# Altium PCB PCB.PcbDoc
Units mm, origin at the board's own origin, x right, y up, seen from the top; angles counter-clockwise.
Board outline 41 x 25.36 mm, 2 copper layers (TOP, BOTTOM), stack 1.586 mm thick; 34 components, 14 nets, 84 pads, 45 vias.
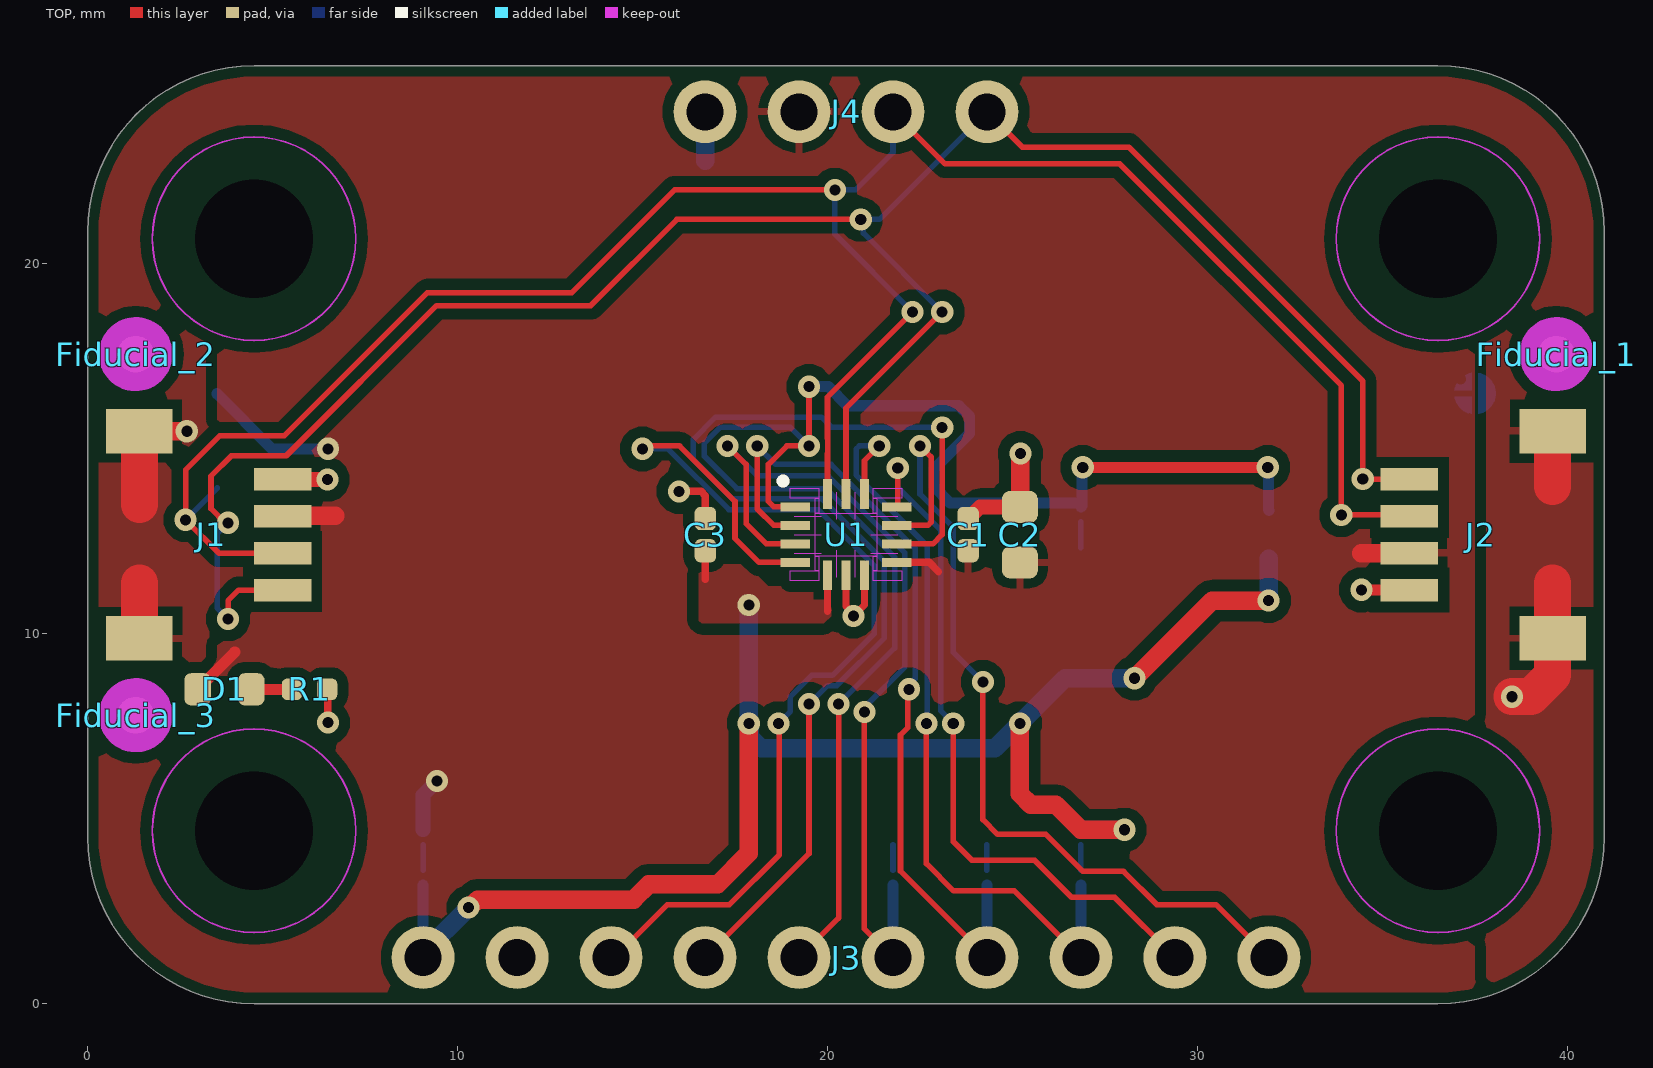
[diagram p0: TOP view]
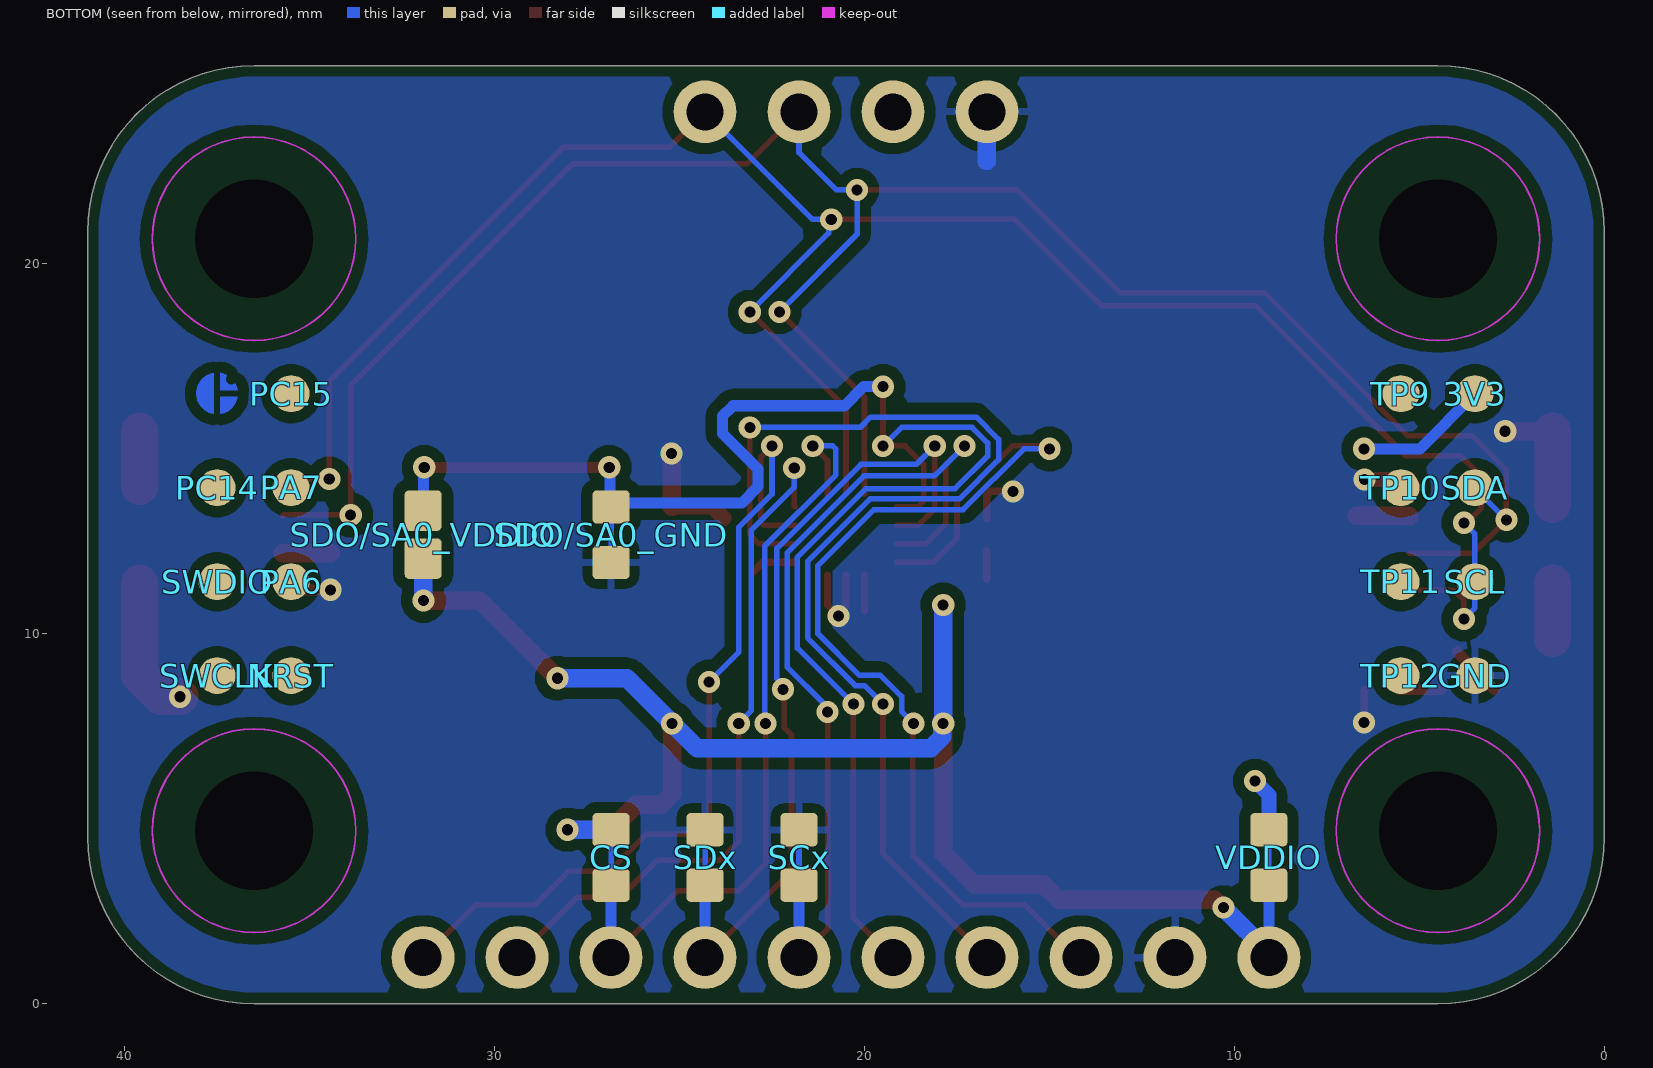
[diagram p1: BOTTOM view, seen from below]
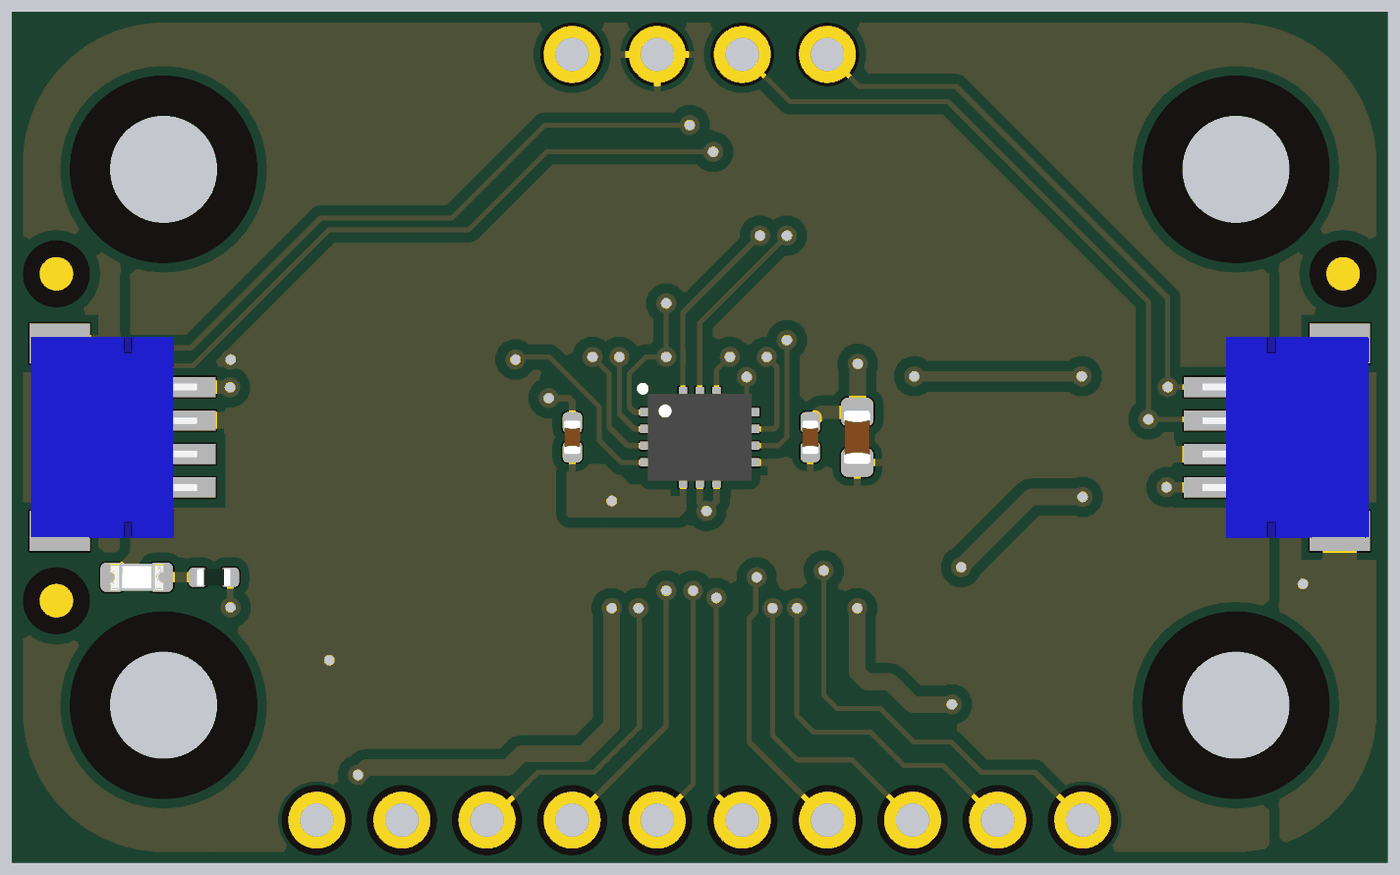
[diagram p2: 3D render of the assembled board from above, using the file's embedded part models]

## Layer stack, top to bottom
Top Solder: solder mask 0.01, Solder Resist, Dk 3.5
TOP: signal copper 0.018
Dielectric: core 1.55, FR-4, Dk 4.8
BOTTOM: signal copper 0.018
Bottom Solder: solder mask 0.01, Solder Resist, Dk 3.5

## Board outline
0,4.5 ccw(c4.5,4.5) 4.5,0 36.5,0 ccw(c36.5,4.5) 41,4.5 41,20.86 ccw(c36.5,20.86) 36.5,25.36 4.5,25.36 ccw(c4.5,20.86) 0,20.86

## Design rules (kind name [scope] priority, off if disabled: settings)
BoardOutlineClearance Mousebites [(ObjectKind = 'Pad') And (Name = 'Free-MOUSEBITE')] p1: gap=0 ignorepadtopadclearanceinfootprint=FALSE
BoardOutlineClearance Silks [(OnLayer('Top Overlay') OR OnLayer('Bottom Overlay'))] p2: gap=0 ignorepadtopadclearanceinfootprint=FALSE
BoardOutlineClearance [All] p3: gap=0.3 ignorepadtopadclearanceinfootprint=FALSE
Clearance [(ObjectKind = 'Text') And (StringType = 'Free') And (Layer = 'TOP') vs IsKeepOut] p1: gap=-2 ignorepadtopadclearanceinfootprint=FALSE
Clearance COPPER_0.3mm [All] p2: gap=0.127 ignorepadtopadclearanceinfootprint=FALSE except(0.3: Arc-Fill Arc-Poly Arc-Region Track-Fill Track-Poly Track-Region SMDPad-Fill SMDPad-Poly SMDPad-Region THPad-Fill THPad-Poly THPad-Region Via-Fill Via-Poly Via-Region Fill-Fill Fill-Poly Fill-Region Poly-Poly Poly-Region Region-Region)
Clearance "Generic clearance 0.15mm" [All] p3: gap=0.15 ignorepadtopadclearanceinfootprint=FALSE
ComponentClearance [All] p1: gap=0.2 collisioncheckmode=3 verticalgap=0 showdistances=TRUE
DiffPairsRouting USB [InDifferentialPairClass('USB')] p1: maxlimit=0.15 minlimit=0.15 mostfreqgap=0.15 toplayer_minwidth=0.15 toplayer_maxwidth=0.21 toplayer_prefwidth=0.2 bottomlayer_minwidth=0.15 bottomlayer_maxwidth=0.21 bottomlayer_prefwidth=0.2 impedanceprofiledriven=TRUE impedanceprofileid={E6B00C31-4C8E-439C-824F-D2B2CDC26F9C} impedanceprofilevalue=90.000000 maxuncoupledlength=12.7
Height [All] p1: minheight=0 maxheight=30 prefheight=12.7
HoleSize [All] p1: absolutevalues=TRUE maxlimit=30 minlimit=0.3 maxpercent=80.000 minpercent=20.000
HoleToHoleClearance [All] p1: gap=0.25 allowstackedmicrovias=FALSE
MinimumAnnularRing [All] p1: minimumring=0.15
NetAntennae NetAntennae_2 [(WithinRoom('SHORTROOM') OR WithinRoom('SHORTROOM_1') OR WithinRoom('SHORTROOM_2') OR WithinRoom('SHORTROOM_3') OR WithinRoom('SHORTROOM_4'))] p1: netantennaetolerance=2
NetAntennae [All] p2: netantennaetolerance=0
PlaneConnect [All] p1: pad.planeconnectstyle=Relief pad.reliefexpansion=0.508 pad.reliefentries=4 pad.reliefconductorwidth=0.254 pad.reliefairgap=0.254 via.planeconnectstyle=Direct via.reliefexpansion=0.508 via.reliefentries=4 via.reliefconductorwidth=0.254 via.reliefairgap=0.254
PolygonConnect [All] p1: thpad.connectstyle=Relief thpad.reliefconductorwidth=0.2 thpad.reliefentries=4 thpad.polygonreliefangle="90 Angle" thpad.airgapwidth=0.254 smdpad.connectstyle=Relief smdpad.reliefconductorwidth=0.2 smdpad.reliefentries=4 smdpad.polygonreliefangle="90 Angle" smdpad.airgapwidth=0.254 via.connectstyle=Direct via.reliefconductorwidth=0.254 via.reliefentries=4 via.polygonreliefangle="90 Angle" via.airgapwidth=0.254
RoomDefinition SHORTROOM_4 [False vs False] p1: confinementstyle=ConfineIn formatcopy=TRUE lockcomponents=FALSE outline 26.45,13.73 27.25,13.73 27.25,11.63 26.45,11.63
RoomDefinition SHORTROOM_3 [False vs False] p2: confinementstyle=ConfineIn formatcopy=TRUE lockcomponents=FALSE outline 8.66,5 9.46,5 9.46,2.9 8.66,2.9
RoomDefinition SHORTROOM_2 [False vs False] p3: confinementstyle=ConfineIn formatcopy=TRUE lockcomponents=FALSE outline 26.45,5.005 27.25,5.005 27.25,2.905 26.45,2.905
RoomDefinition SHORTROOM_1 [False vs False] p4: confinementstyle=ConfineIn formatcopy=TRUE lockcomponents=FALSE outline 23.91,5.005 24.71,5.005 24.71,2.905 23.91,2.905
RoomDefinition SHORTROOM [False vs False] p5: confinementstyle=ConfineIn formatcopy=TRUE lockcomponents=FALSE outline 21.37,5.005 22.17,5.005 22.17,2.905 21.37,2.905
RoomDefinition TOP [InComponentClass('TOP')] p6: confinementstyle=ConfineIn formatcopy=TRUE lockcomponents=FALSE outline 45.1,1.2 58.1,1.2 58.1,13.6 45.1,13.6
RoutingVias StandardVias [All] p1: holewidth=0.3 width=0.6 viastyle="Through Hole" minholewidth=0.3 minwidth=0.6 maxholewidth=0.3 maxwidth=0.6
SMDToCorner [All] p1: distance=39370
ShortCircuit short_jumper [(WithinRoom('SHORTROOM') OR WithinRoom('SHORTROOM_1') OR WithinRoom('SHORTROOM_2') OR WithinRoom('SHORTROOM_3') OR WithinRoom('SHORTROOM_4')) vs (WithinRoom('SHORTROOM') OR WithinRoom('SHORTROOM_1') OR WithinRoom('SHORTROOM_2') OR WithinRoom('SHORTROOM_3') OR WithinRoom('SHORTROOM_4'))] p1: allowed=TRUE
ShortCircuit ShortCircuit_1 [(ObjectKind = 'Pad') And (Layer = 'TOP') And (Net = 'GND') And (Name = 'SJ2-2')] p2: allowed=TRUE
ShortCircuit [All] p3: allowed=FALSE
SilkToSilkClearance [All] p1: silktosilkclearance=0.2
SilkToSolderMaskClearance [IsPad] p1: minsilkscreentomaskgap=0.15 clearancetoexposedcopper=TRUE
SolderMaskExpansion VIAtented [IsVia] p1: expansion=0.102 istentingtop=TRUE
SolderMaskExpansion [All] p2: expansion=0.05 istentingtop=FALSE
UnConnectedPin [All] p1:
UnRoutedNet [NOT WithinRoom('K36')] p1: checkbadconnections=TRUE
ViasUnderSMD [All] p1: allowed=FALSE
Width StandardTraces [All] p1: maxlimit=5 minlimit=0.15 preferedwidth=0.15 minimp=50.000000 maximp=50.000000 favimp=50.000000
19 further rules are at their usual default settings.

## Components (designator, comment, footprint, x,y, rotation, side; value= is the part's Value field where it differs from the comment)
3V3 "Test point 1.00mm" TP-1.00MM 3.5,16.49 r90 bottom
C1 "0402B104K160CT" CAP-0402 23.8,12.68 r90 top value=100nF
C2 "GRM188R61C475KAAJD" CAP-0603 25.2,12.68 r270 top value=4.7µF
C3 "0402B104K160CT" CAP-0402 16.7,12.68 r90 top value=100nF
CS "SOLDER JUMPER CLOSED 0603" "SJ 0603 CLOSED" 26.85,3.955 r270 bottom
D1 "HSMG-C190" LEDC1608X80N-AK 3.7,8.5 r180 top
Fiducial_1 "Fiducial mark 1mm" "Fiducial mark 1mm-Footprint-1" 39.7,17.56 r270 top
Fiducial_2 "Fiducial mark 1mm" "Fiducial mark 1mm-Footprint-1" 1.3,17.56 r270 top
Fiducial_3 "Fiducial mark 1mm" "Fiducial mark 1mm-Footprint-1" 1.3,7.8 r270 top
GND "Test point 1.00mm" TP-1.00MM 3.5,8.87 r90 bottom
J1 "SM04B-SRSS-TB(LF)(SN)" SM04B-SRSS-TB(LF)(SN)-Footprint-1 3.337,12.68 r90 top locked
J2 "SM04B-SRSS-TB(LF)(SN)" SM04B-SRSS-TB(LF)(SN)-Footprint-1 37.663,12.68 r270 top locked
J3 "HEADER TH 2.54mm VERT. 1x010POS" "PIN HEADER 2.54mm VERT. 1x10POS" 20.5,1.25 r0 top
J4 "HEADER TH 2.54mm VERT. 1x004POS" "PIN HEADER 2.54mm VERT. 1x4POS-Footprint-1" 20.5,24.11 r0 top
NRST "Test point 1.00mm" TP-1.00MM 35.5,8.87 r180 bottom
PA6 "Test point 1.00mm" TP-1.00MM 35.5,11.41 r180 bottom
PA7 "Test point 1.00mm" TP-1.00MM 35.5,13.95 r180 bottom
PC14 "Test point 1.00mm" TP-1.00MM 37.5,13.95 r180 bottom
PC15 "Test point 1.00mm" TP-1.00MM 35.5,16.49 r180 bottom
R1 "CRCW04021K00FKEDC" RES-0402 6,8.5 r180 top value=1k
SCL "Test point 1.00mm" TP-1.00MM 3.5,11.41 r90 bottom
SCx "SOLDER JUMPER CLOSED 0603" "SJ 0603 CLOSED" 21.77,3.955 r270 bottom
SDA "Test point 1.00mm" TP-1.00MM 3.5,13.95 r90 bottom
SDO/SA0_GND "SOLDER JUMPER CLOSED 0603" "SJ 0603 CLOSED" 26.85,12.68 r90 bottom
SDO/SA0_VDDIO "SOLDER JUMPER OPEN 0603" SJ 31.93,12.68 r90 bottom
SDx "SOLDER JUMPER CLOSED 0603" "SJ 0603 CLOSED" 24.31,3.955 r270 bottom
SWCLK "Test point 1.00mm" TP-1.00MM 37.5,8.87 r180 bottom
SWDIO "Test point 1.00mm" TP-1.00MM 37.5,11.41 r180 bottom
TP9 "Test point 1.00mm" TP-1.00MM 5.5,16.49 r0 bottom
TP10 "Test point 1.00mm" TP-1.00MM 5.5,13.95 r0 bottom
TP11 "Test point 1.00mm" TP-1.00MM 5.5,11.41 r0 bottom
TP12 "Test point 1.00mm" TP-1.00MM 5.5,8.87 r0 bottom
U1 "LSM6DSOXTR" LSM6DSOXTR 20.5,12.68 r0 top
VDDIO "SOLDER JUMPER CLOSED 0603" "SJ 0603 CLOSED" 9.07,3.955 r90 bottom

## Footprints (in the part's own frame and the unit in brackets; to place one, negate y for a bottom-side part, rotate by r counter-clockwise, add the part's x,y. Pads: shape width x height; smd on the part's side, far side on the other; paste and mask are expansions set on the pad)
CAP-0402 [mm] "Chip Capacitor, 2-Leads, Body  0402 (in) 1005 (mm), IPC Medium Density"
  rrect52% 0.63x0.58 smd mask+0.05: 1(-0.435,0) 2(0.435,0)
  body extent -0.5,-0.25 0.5,0.25, height 0.5
CAP-0603 [mm] "Chip Capacitor, Body 0603 imperial,1.6x0.8mm, IPC High Density"
  rrect51% 0.87x0.97 smd mask+0.05: 1(-0.75,0) 2(0.75,0)
  body extent -0.8,-0.4 0.8,0.4, height 0.8
"Fiducial mark 1mm-Footprint-1" [mm]
  round 1 smd paste-10 mask+0.5: 1(0,0)
  TOP keep-out circle w1: c0,0 r0.5
LEDC1608X80N-AK [mm]
  rrect50% 0.72x0.87 smd: A(0.725,0) C(-0.725,0)
  body extent -0.8,-0.4 0.8,0.4, height 0.79
LSM6DSOXTR [mm]
  rect 0.8x0.25 smd mask+0.05: 1(-1.375,0.75) 2(-1.375,0.25) 3(-1.375,-0.25) 4(-1.375,-0.75) 8(1.375,-0.75) 9(1.375,-0.25) 10(1.375,0.25) 11(1.375,0.75)
  rect 0.25x0.8 smd mask+0.05: 5(-0.5,-1.1) 6(0,-1.1) 7(0.5,-1.1) 12(0.5,1.1) 13(0,1.1) 14(-0.5,1.1)
  TOP keep-out region: -0.83,-0.98 -0.83,-0.58 -0.74,-0.58 -0.74,-0.98
  TOP keep-out region: 0.74,-0.98 0.74,-0.58 0.83,-0.58 0.83,-0.98
  TOP keep-out region: 0.74,0.58 0.74,0.98 0.83,0.98 0.83,0.58
  TOP keep-out region: -0.83,0.58 -0.83,0.98 -0.74,0.98 -0.74,0.58
  TOP keep-out region: -1.5,-1.25 -1.5,-0.98 -0.74,-0.98 -0.74,-1.25
  TOP keep-out region: 0.74,-1.25 0.74,-0.98 1.5,-0.98 1.5,-1.25
  TOP keep-out region: 0.74,0.98 0.74,1.25 1.5,1.25 1.5,0.98
  TOP keep-out region: -1.5,0.98 -1.5,1.25 -0.74,1.25 -0.74,0.98
  TOP keep-out region: -0.83,-0.58 -0.83,0.58 0.83,0.58 0.83,-0.58
  TOP keep-out lines w0.01: -1.4,-0.5 -0.67,-0.5 ; -1.4,0 -0.67,0 ; -1.4,0.5 -0.67,0.5 ; -0.25,-1.15 -0.25,-0.42 ; -0.25,0.42 -0.25,1.15 ; 0.25,-1.15 0.25,-0.42 ; 0.25,0.42 0.25,1.15 ; 0.67,-0.5 1.4,-0.5 ; 0.67,0 1.4,0 ; 0.67,0.5 1.4,0.5
  silkscreen extent -1.75,1.4 -1.65,1.5, body extent -1.55,-1.3 1.55,1.3, height 0.86
"PIN HEADER 2.54mm VERT. 1x4POS-Footprint-1" [mm]
  round 1.7 hole 1 mask+0.1: 1(-3.81,0) 2(-1.27,0) 3(1.27,0) 4(3.81,0)
"PIN HEADER 2.54mm VERT. 1x10POS" [mm]
  round 1.7 hole 1 mask+0.2: 1(-11.43,0) 2(-8.89,0) 3(-6.35,0) 4(-3.81,0) 5(-1.27,0) 6(1.27,0) 7(3.81,0) 8(6.35,0) 9(8.89,0) 10(11.43,0)
RES-0402 [mm] "Chip Resistor, 2-Leads, Body  0402 (in) 1005 (mm), IPC Medium Density"
  rrect51% 0.55x0.58 smd mask+0.05: 1(-0.475,0) 2(0.475,0)
  body extent -0.5,-0.25 0.5,0.25, height 0.34
SJ [mm]
  rrect25% 1.1x1 smd paste-2539.97 mask+0.1: 1(0.65,0) 2(-0.65,0)
"SJ 0603 CLOSED" [mm]
  rrect25% 0.9x1 smd paste-2539.97 mask+0.1: 1(0.75,0) 2(-0.75,0)
  TOP lines w0.15: 0.35,0 -0.35,0
SM04B-SRSS-TB(LF)(SN)-Footprint-1 [mm]
  rect 0.6x1.55 smd mask+0.05: 1(1.5,-1.937) 2(0.5,-1.937) 3(-0.5,-1.937) 4(-1.5,-1.937)
  rect 1.2x1.8 smd mask+0.05: FIX(-2.8,1.938) FIX(2.8,1.938)
  body extent -3,-2.16 3,2.8, height 2.98
TP-1.00MM [mm]
  rrect100% 1x1 smd paste-2.54: X(0,0)

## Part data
3V3 GND NRST PA6 PA7 PC14 PC15 SCL SDA SWCLK SWDIO TP9 TP10 TP11 TP12: library part UT0013-A.6, Manufacturer="This is not a component"
C1 C3: library part C0012-A.15, "CAP CHIP 0402 100nF 10% 16V X7R", Case Code (Imperial)=0402, Dielectric=X7R, Manufacturer=Walsin, Tolerance=10%, Voltage=16V
C2: library part C0054-A.16, "CAP CHIP 0603 4.7uF 10% 16V X5R", Case Code (Imperial)=0603, Dielectric=X5R, Manufacturer=Murata, Manufacturer 3="Samsung Electro-Mechanics", Part number 2=GRM188R61C475KE11D, Part number 3=CL10A475KO8NNNC, Tolerance=10%, Voltage=16V
CS SCx SDO/SA0_GND SDx VDDIO: library part UT0039-A.3
D1: library part L0009-A.5, "LED SMD 0603 GREEN/568 15mcd 120^", Manufacturer=Broadcom
Fiducial_1 Fiducial_2 Fiducial_3: library part UT0023-A.7, "Fiducial mark 1mm clearance 2mm"
J1 J2: library part J0005-A.2, "CONN JST 4POS SIDE 1MM TIN QWIIC", Manufacturer=JST
J3: library part J0169-A.8
J4: library part J0162-A.5
R1: library part R0007-A.24, "RES CHIP 0402 1k 1% 1/16W", Case Code (Imperial)=0402, Manufacturer=Vishay, Power=62.5mW, Temperature Coefficient=100ppm, Tolerance=1%
SDO/SA0_VDDIO: library part UT0038-A.4
U1: library part U0179-A.10, "IC IMU 6 axis, 9kB data buffering, event/tilt detection, sensor hub, VDD 1.71V to 3.6V, VDDIO 1.62V to 3.6V, I2C/SPI, auxiliary SPI, LGA14 3x2.5x0.86mm", Manufacturer="ST Microelectronics"

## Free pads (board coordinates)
  round 3 hole 3.2 unplated paste-2539.97 mask-2539.97: MH(4.5,4.68)
  round 3 hole 3.2 unplated paste-2539.97 mask+1.3: MH(4.5,20.68) MH(36.5,4.68) MH(36.5,20.68)

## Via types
v1: diameter 0.6, hole 0.3, TOP to BOTTOM, tented both sides, 44 vias
v2: diameter 0.6, hole 0.3, TOP to BOTTOM, 1 vias

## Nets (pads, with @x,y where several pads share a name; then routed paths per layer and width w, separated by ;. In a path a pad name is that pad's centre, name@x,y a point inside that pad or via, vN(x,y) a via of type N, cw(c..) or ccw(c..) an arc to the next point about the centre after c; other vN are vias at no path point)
+3V3: 3V3.X C1.1 C2.2 D1.A J1.2 J2.2 J4.2 U1.8 VDDIO.1 | length 10.5
  TOP w0.2: U1.8 22.75,11.93 23,11.68
  TOP w0.3: D1.A 3.98,9.505
  TOP w0.5: J1.2 5.284,13.19 6.69,13.19 ; 34.42,12.18 J2.2
  BOTTOM w0.3: 3V3.X 4.99,15 v1(6.5,15)
  BOTTOM w0.4: VDDIO.1 9.07,5.647 v1(9.447,6.024)
CS_1: CS.1 J3.8 U1.12 | length 21.3
  TOP w0.15: U1.12 21,14.68 v1(21.4,15.08) ; v1(22.673,7.58) 22.673,3.787 23.41,3.05 25.05,3.05 J3.8
  BOTTOM w0.15: v1(21.4,15.08) 20.861,15.08 20.773,14.992 20.773,14.295 22.702,12.366 22.702,7.609 v1(22.673,7.58)
  BOTTOM w0.3: J3.8 CS.1
GND: C1.2 C2.1 C3.2 GND.X J1.1 J1.FIX J2.1 J2.FIX J3.2 J4.1 R1.1 SCx.2 SDO/SA0_GND.2 SDx.2 U1.6 U1.7 | length 21.6
  TOP w0.2: R1.1 6.488,8.488 6.488,7.612 v1(6.5,7.6) ; v1(15.99,13.85) 16.583,13.85 16.7,13.733 C3.2 ; U1.6 20.5,10.742 20.6,10.641 20.6,10.58 v1(20.7,10.48) 21,10.78 U1.7
  TOP w0.3: v1(34.43,11.19) 34.435,11.185 35.721,11.185 J2.1
  TOP w0.4: J1.1 5.279,14.175 6.479,14.175 v1(6.484,14.171) ; C1.2 23.8,13.14 23.89,13.23 23.924,13.23 24.124,13.43 24.965,13.43 C2.1
  TOP w0.5: J1.FIX@1.399,15.48 2.678,15.48 v1(2.683,15.475) ; C2.1 25.208,13.438 25.208,14.866 v1(25.215,14.874)
  TOP w1: J1.FIX@1.399,9.88 1.399,11.379 ; 1.399,13.499 J1.FIX@1.399,15.48 ; v1(38.5,8.3) 39.015,8.3 39.601,8.886 J2.FIX@39.601,9.88 ; J2.FIX@39.6,9.881 39.6,11.38 ; 39.601,13.981 J2.FIX@39.601,15.48
  BOTTOM w0.5: 16.69,22.79 J4.1
INT1_1: J3.3 U1.4 | length 28.5
  TOP w0.15: J3.3 14.243,1.25 15.673,2.68 17.35,2.68 18.696,4.026 18.696,7.557 v2(18.673,7.58) ; v1(15,15) 15.08,15.08 16,15.08 17.5,13.58 17.5,12.58 18.15,11.93 U1.4
  BOTTOM w0.15: v1(15,15) 15.69,15 17.332,13.358 19.747,13.358 21.259,11.846 21.259,10.003 20.135,8.879 19.569,8.879 18.998,8.308 18.998,7.905 v2(18.673,7.58)
INT2_1: J3.4 U1.9 | length 31
  TOP w0.15: J3.4 19.5,4.06 v1(19.5,8.1) ; U1.9 22.85,12.43 23.1,12.68 v1(23.1,15.58)
  BOTTOM w0.15: v1(19.5,8.1) 20.002,8.602 20.249,8.602 21.536,9.888 21.536,11.961 19.85,13.646 17.435,13.646 16.373,14.709 16.373,15.255 16.977,15.859 19.838,15.859 20.115,15.582 23.098,15.582 v1(23.1,15.58)
NetD1_C: D1.C R1.2 | length 1.1
  TOP w0.3: D1.C R1.2
OCS_Aux_1: J3.10 U1.10 | length 23.2
  TOP w0.15: U1.10 22.712,12.93 22.8,13.018 22.8,14.78 v1(22.5,15.08) ; v1(24.2,8.7) 24.2,4.98 24.6,4.58 25.9,4.58 26.9,3.58 28,3.58 28.9,2.68 30.5,2.68 J3.10
  BOTTOM w0.15: v1(22.5,15.08) 22.5,13.778 23.4,12.878 23.4,9.5 v1(24.2,8.7)
SCL_1: J1.4 J2.4 J4.4 SCL.X U1.13 | length 58
  TOP w0.15: v1(3.8,10.4) 3.8,10.9 4.08,11.18 J1.4 ; v1(3.8,13) 3.723,13 3.337,13.386 3.337,14.262 3.888,14.813 5.371,14.813 9.431,18.874 13.601,18.874 15.927,21.2 v1(20.9,21.2) ; U1.13 20.5,16.1 v1(23.1,18.7) ; J4.4 25.263,23.157 28.143,23.157 34.468,16.832 v1(34.468,14.182) J2.4 J2.4
  BOTTOM w0.15: v1(3.8,10.4) 3.5,10.7 3.5,12.7 v1(3.8,13) ; v1(23.1,18.7) 20.971,20.829 20.971,21.129 v1(20.9,21.2) 21.4,21.2 J4.4
SCx_1: J3.6 SCx.1 U1.3 | length 23.5
  TOP w0.15: v1(17.3,15.08) 17.8,14.58 17.8,12.98 18.35,12.43 U1.3 ; v1(20.996,7.884) 20.996,2.024 J3.6
  BOTTOM w0.15: v1(17.3,15.08) 18.113,14.267 20.013,14.267 22.091,12.189 22.091,9.101 v1@21.086,8.096 ; v1(20.996,7.884) 20.996,8.006 v1@21.086,8.096
  BOTTOM w0.3: J3.6 SCx.1
SDA_1: J1.3 J2.3 J4.3 SDA.X U1.14 | length 59.9
  TOP w0.15: 2.65,14.44 v1(2.65,13.082) 3.554,12.178 3.895,12.178 3.897,12.18 J1.3 ; 2.66,14.44 3.569,15.349 5.313,15.349 9.187,19.224 13.092,19.224 15.868,22 v1(20.2,22) ; U1.14 20,14.87 20.002,14.872 20.002,15.288 20,15.29 20,16.4 v1(22.3,18.7) ; J4.3 23.18,22.7 27.9,22.7 33.887,16.713 v1(33.887,13.215) 35.69,13.215 J2.3
  BOTTOM w0.15: v1(2.65,13.082) 3.5,13.932 SDA.X ; J4.3 21.77,23.01 20.76,22 v1(20.2,22) 20.2,20.8 v1(22.3,18.7)
SDO/SA0_1: J3.5 SDO/SA0_GND.1 SDO/SA0_VDDIO.1 U1.1 | length 44.7
  TOP w0.15: U1.1 18.55,13.43 18.4,13.58 18.4,14.58 18.9,15.08 v1(19.5,15.08) v1(19.5,16.68) ; J3.5 20.3,2.32 v1(20.3,8.1)
  TOP w0.3: v1(26.9,14.5) v1(31.9,14.5)
  BOTTOM w0.15: v1(19.5,15.08) 18.998,15.582 17.092,15.582 16.673,15.163 16.673,14.8 17.55,13.923 19.965,13.923 21.814,12.074 21.814,9.614 v1(20.3,8.1)
  BOTTOM w0.3: v1(19.5,16.68) 20.025,16.68 20.541,16.164 23.558,16.164 23.836,15.887 23.836,15.417 22.873,14.455 22.873,13.977 23.311,13.539 SDO/SA0_GND.1@26.752,13.539 ; SDO/SA0_GND.1 26.875,13.455 26.875,14.475 v1(26.9,14.5) ; v1(31.9,14.5) 31.915,14.485 31.915,13.345 SDO/SA0_VDDIO.1
SDO_Aux_1: J3.9 U1.11 | length 19.1
  TOP w0.15: U1.11 21.9,13.455 v1(21.9,14.48) ; v1(23.4,7.58) 23.4,4.38 23.9,3.88 25.6,3.88 26.6,2.88 27.76,2.88 J3.9
  BOTTOM w0.15: v1(21.9,14.48) 21.9,13.959 23.057,12.802 23.057,7.923 v1(23.4,7.58)
SDx_1: J3.7 SDx.1 U1.2 | length 22.5
  TOP w0.15: v1(18.1,15.08) 18.1,13.38 18.55,12.93 U1.2 ; v1(22.2,8.5) 22.171,8.471 22.171,7.465 21.973,7.267 21.973,3.587 J3.7
  BOTTOM w0.15: v1(18.1,15.08) 18.602,14.578 20.099,14.578 22.368,12.309 22.368,8.79 22.2,8.622 v1(22.2,8.5)
  BOTTOM w0.3: J3.7 SDx.1
VDDIO: C3.1 CS.2 J3.1 SDO/SA0_VDDIO.2 U1.5 VDDIO.2 | length 44.1
  TOP w0.2: 16.7,11.48 C3.1 ; 20,10.615 U1.5
  TOP w0.5: v1(10.3,2.6) 10.327,2.6 10.545,2.818 14.76,2.818 15.168,3.227 17.027,3.227 17.873,4.073 v1(17.873,7.58) ; v1(25.2,7.58) 25.2,5.673 25.493,5.38 26.175,5.38 26.85,4.705 v1(28.025,4.705) ; v1(28.3,8.8) 30.399,10.899 v1(31.923,10.899)
  BOTTOM w0.3: J3.1 VDDIO.2
  BOTTOM w0.5: J3.1 9.07,1.37 v1@10.281,2.581 ; v1@17.873,7.553 v1(17.873,10.78) ; v1(17.873,7.58) 17.892,7.561 17.892,7.227 18.216,6.903 24.523,6.903 26.42,8.8 v1(28.3,8.8) ; CS.2 v1(28.025,4.705) ; v1(31.923,10.899) 31.927,10.903 31.927,12.027 SDO/SA0_VDDIO.2
pads on no net: Fiducial_1.1 Fiducial_2.1 Fiducial_3.1 NRST.X PA6.X PA7.X PC14.X PC15.X SWCLK.X SWDIO.X TP9.X TP10.X TP11.X TP12.X

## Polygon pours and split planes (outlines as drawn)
GND on TOP "NONET_L04_P-001" (solid, remove dead copper, pour order 5): 0,4.5 ccw(c4.5,4.5) 4.5,0 36.5,0 ccw(c36.5,4.5) 41,4.5 41,20.86 ccw(c36.5,20.86) 36.5,25.36 4.5,25.36 ccw(c4.5,20.86) 0,20.86
+3V3 on TOP "NONET_L04_P-001" (solid, remove dead copper, pour order 3): 0,4.5 ccw(c4.5,4.5) 4.5,0 36.5,0 ccw(c36.5,4.5) 41,4.5 41,20.86 ccw(c36.5,20.86) 36.5,25.36 4.5,25.36 ccw(c4.5,20.86) 0,20.86
VDDIO on TOP "VDDIO_L01_P000" (solid, remove dead copper, pour order 0): 20.2,12.08 20.2,10.58 19.9,10.28 16.6,10.28 16.522,10.358 16.522,11.88 17.8,11.88 18.4,11.28 19.7,11.28 19.7,12.08
GND on TOP "NONET_L04_P-001" (solid, remove dead copper, pour order 2): 0,25.36 0,0 3.2,0 3.2,25.36
GND on TOP "NONET_L04_P-001" (solid, remove dead copper, pour order 1): 41,25.36 41,0 37.8,0 37.8,25.36
GND on BOTTOM "NONET_L04_P-001" (solid, remove dead copper, pour order 4): 0,4.5 ccw(c4.5,4.5) 4.5,0 36.5,0 ccw(c36.5,4.5) 41,4.5 41,20.86 ccw(c36.5,20.86) 36.5,25.36 4.5,25.36 ccw(c4.5,20.86) 0,20.86

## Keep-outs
Keep-Out Layer:
  circle w0.05: c4.5,20.68 r2.75
  circle w0.05: c4.5,4.68 r2.75
  circle w0.05: c36.5,20.68 r2.75
  circle w0.05: c36.5,4.68 r2.75

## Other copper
BOTTOM:
  region: 37.415,16.266 37.415,15.955 37.408,15.955 37.408,15.949 37.382,15.949 37.382,15.955 37.375,15.955 37.375,15.962 37.335,15.962 37.335,15.969 37.309,15.969 37.309,15.975 37.302,15.975 37.302,15.982 37.289,15.982 37.289,15.989 37.282,15.989 37.282,15.995 37.269,15.995 37.269,15.989 37.256,15.989 37.256,16.002 37.236,16.002 37.236,16.008 37.229,16.008 37.229,16.015 37.223,16.015 37.223,16.022 37.203,16.022 37.203,16.028 37.196,16.028 37.196,16.035 37.183,16.035 37.183,16.041 37.177,16.041 37.177,16.048 37.17,16.048 37.17,16.055 37.157,16.055 37.157,16.068 37.137,16.068 37.137,16.075 37.13,16.075 37.13,16.081 37.124,16.081 37.124,16.088 37.117,16.088 37.117,16.094 37.11,16.094 37.11,16.101 37.104,16.101 37.104,16.108 37.097,16.108 37.097,16.114 37.091,16.114 37.091,16.121 37.084,16.121 37.084,16.127 37.077,16.127 37.077,16.134 37.071,16.134 37.071,16.154 37.064,16.154 37.064,16.161 37.057,16.161 37.057,16.167 37.051,16.167 37.051,16.174 37.044,16.174 37.044,16.187 37.038,16.187 37.038,16.194 37.031,16.194 37.031,16.2 37.024,16.2 37.024,16.207 37.018,16.207 37.018,16.227 37.011,16.227 37.011,16.247 36.998,16.247 36.998,16.266 36.991,16.266 36.991,16.286 36.978,16.286 36.978,16.319 36.971,16.319 36.971,16.326 36.965,16.326 36.965,16.339 36.971,16.339 36.971,16.346 36.965,16.346 36.965,16.352 36.958,16.352 36.958,16.405 37.408,16.405 37.408,16.399 37.415,16.399 37.415,16.273
  region: 36.978,16.584 36.945,16.584 36.945,16.591 36.952,16.591 36.952,16.597 36.958,16.597 36.958,16.65 36.965,16.65 36.965,16.657 36.971,16.657 36.971,16.663 36.965,16.663 36.965,16.677 36.971,16.677 36.971,16.683 36.978,16.683 36.978,16.71 36.985,16.71 36.985,16.716 36.991,16.716 36.991,16.729 36.998,16.729 36.998,16.749 37.005,16.749 37.005,16.756 37.011,16.756 37.011,16.763 37.024,16.763 37.024,16.756 37.038,16.756 37.038,16.749 37.044,16.749 37.044,16.743 37.064,16.743 37.064,16.736 37.071,16.736 37.071,16.729 37.157,16.729 37.157,16.743 37.19,16.743 37.19,16.749 37.196,16.749 37.196,16.756 37.203,16.756 37.203,16.763 37.21,16.763 37.21,16.769 37.216,16.769 37.216,16.776 37.223,16.776 37.223,16.782 37.229,16.782 37.229,16.789 37.236,16.789 37.236,16.796 37.243,16.796 37.243,16.802 37.249,16.802 37.249,16.809 37.256,16.809 37.256,16.829 37.263,16.829 37.263,16.941 37.256,16.941 37.256,16.961 37.249,16.961 37.249,16.968 37.243,16.968 37.243,16.974 37.236,16.974 37.236,16.987 37.243,16.987 37.243,16.994 37.263,16.994 37.263,17.007 37.282,17.007 37.282,17.014 37.289,17.014 37.289,17.02 37.315,17.02 37.315,17.027 37.349,17.027 37.349,17.04 37.388,17.04 37.388,17.047 37.395,17.047 37.395,17.054 37.408,17.054 37.408,17.047 37.415,17.047 37.415,16.591 37.408,16.591 37.408,16.584 36.985,16.584
  region: 197 vertices and 0 holes, not listed, extent 37.593,15.949 38.056,17.047

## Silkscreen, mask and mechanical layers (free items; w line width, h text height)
Top Solder:
  circle w2.8: c4.5,4.68 r1.4
Bottom Solder:
  circle w1.9: c4.5,4.68 r0.95
Route Tool Path:
  lines w2: -1,8.498 -1,16.86 ; 42,4.5 cw(c36.5,4.5) 36.5,-1 ; 42,8.498 42,16.86 ; -1,4.498 ccw(c4.5,4.5) 4.498,-1 ; -1,4.498 cw(c4.5,4.5) -1,4.5 ccw(c0,4.5) -1,4.498 ; -1,20.86 cw(c4.5,20.86) 4.5,26.36 ; -1,20.86 -1,20.86 ; 4.498,-1 ccw(c4.5,4.5) 4.5,-1 ; 4.498,-1 ccw(c4.5,0) 4.5,-1 ; 4.5,-1 36.5,-1 ; 4.5,26.36 36.5,26.36 ; 4.5,26.36 4.5,26.36 ; 36.5,-1 36.5,-1 ; 36.5,26.36 cw(c36.5,20.86) 36.502,26.36 ; 36.5,26.36 cw(c36.5,25.36) 36.502,26.36 ; 36.502,26.36 cw(c36.5,20.86) 42,20.863 ; 42,20.863 cw(c41,20.86) 42,20.86 ccw(c36.5,20.86) 42,20.863
Board:
  the board outline again, w0.05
